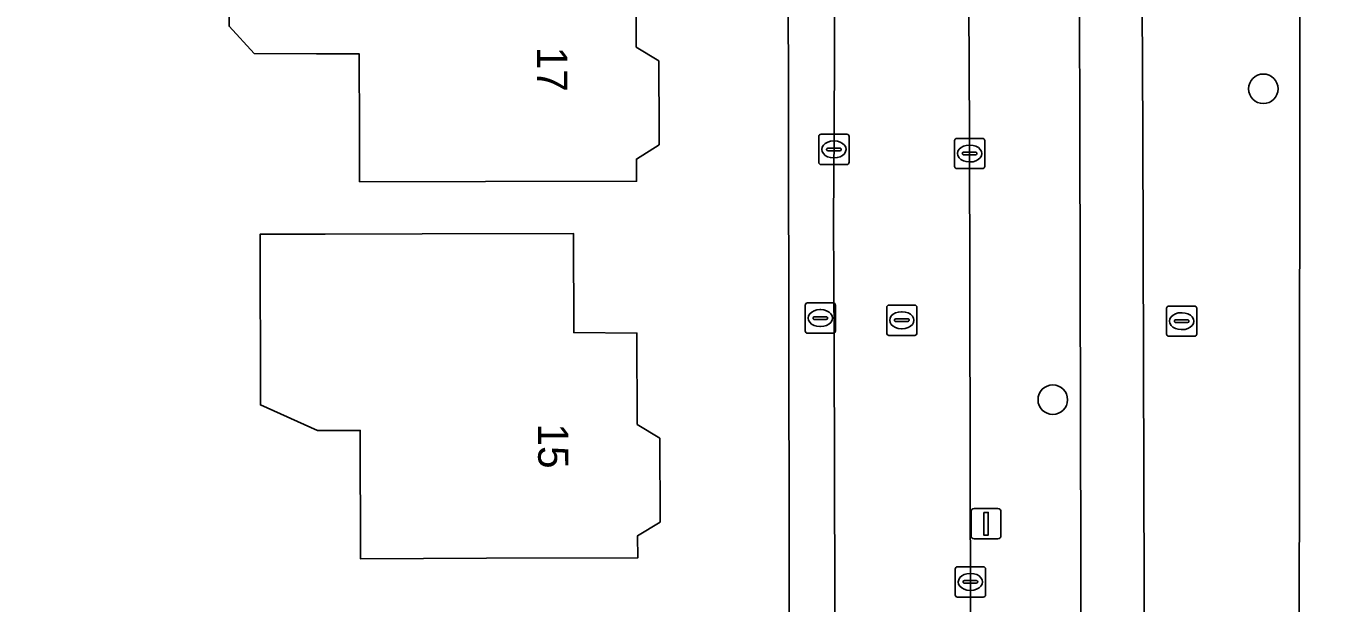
# Model space of a CAD drawing. Extents: x 160455 to 162082, y 388339 to 389736.
# Drawn here: x 160990.1 to 161032.93, y 388484.44 to 388503.52 of the extents above; entities that cross this region are included whole.
import ezdxf

# ---------------------------------------------------------------- set-up
doc = ezdxf.new("R2010")
doc.units = 0
for name, color, linetype in [('IMGEO_Berm_groen', 7, 'Continuous'), ('IMGEO_Boom', 7, 'Continuous'), ('IMGEO_Brandkraan', 7, 'Continuous'), ('IMGEO_Erf', 7, 'Continuous'), ('IMGEO_Fietspad_gesloten', 7, 'Continuous'), ('IMGEO_Kolk', 7, 'Continuous'), ('IMGEO_Lichtmast', 7, 'Continuous'), ('IMGEO_Pand', 7, 'Continuous'), ('IMGEO_Pand_nummerreeks', 7, 'Continuous'), ('IMGEO_Rijbaan_lokaal_gesloten', 7, 'Continuous'), ('IMGEO_Rijbaan_lokaal_open', 7, 'Continuous'), ('IMGEO_Rioolput', 7, 'Continuous'), ('IMGEO_Voetpad_open', 7, 'Continuous')]:
    doc.layers.add(name, color=color, linetype=linetype)

msp = doc.modelspace()

# ---------------------------------------------------------------- linework, layer by layer
at = {"layer": 'IMGEO_Berm_groen'}
msp.add_lwpolyline([(161032.227, 388500), (161032.231, 388503.917), (161032.193, 388520.283), (161029.121, 388520.276), (161029.136, 388504.228), (161027.02, 388504.221), (161027.033, 388500), (161027.148, 388462.179), (161031.576, 388462.237), (161031.753, 388467.74), (161032.004, 388475.58), (161032.208, 388481.936)], close=True, dxfattribs=at)
for points in [[(161024.953, 388500), (161024.943, 388504.232), (161021.289, 388504.243), (161021.304, 388500), (161021.377, 388467.669), (161021.401, 388466.075), (161021.412, 388465.493)], [(161022.511, 388462.16), (161025.043, 388462.172), (161024.953, 388500)]]:
    msp.add_lwpolyline(points, dxfattribs=at)
at = {"layer": 'IMGEO_Boom'}
for centre in [(161031.022, 388501.444), (161024.06, 388491.163)]:
    msp.add_circle(centre, 0.489, dxfattribs=at)
at = {"layer": 'IMGEO_Brandkraan'}
for p, q in [((161015.947, 388494.362), (161016.799, 388494.362)), ((161015.872, 388493.436), (161015.872, 388494.288)), ((161016.174, 388493.905), (161016.572, 388493.905)), ((161016.36, 388494.142), (161016.385, 388494.142)), ((161016.873, 388494.288), (161016.873, 388493.436)), ((161016.131, 388493.856), (161016.131, 388493.868)), ((161016.569, 388493.819), (161016.171, 388493.819)), ((161016.383, 388493.582), (161016.358, 388493.582)), ((161016.615, 388493.868), (161016.615, 388493.856)), ((161016.799, 388493.362), (161015.947, 388493.362))]:
    msp.add_line(p, q, dxfattribs=at)
for points in [[(161015.947, 388494.362), (161016.799, 388494.362)], [(161015.872, 388493.436), (161015.872, 388494.288)], [(161016.873, 388494.288), (161016.873, 388493.436)], [(161016.799, 388493.362), (161015.947, 388493.362)]]:
    msp.add_lwpolyline(points, dxfattribs=at)
for centre, radius, start, end in [((161015.949, 388494.286), 0.0765, 91.552, 178.448), ((161015.949, 388494.286), 0.0765, 91.552, 178.448), ((161016.797, 388494.286), 0.0765, 1.552, 88.448), ((161016.797, 388494.286), 0.0765, 1.552, 88.448), ((161016.171, 388493.865), 0.0403, 85.8775, 175.7526), ((161016.576, 388493.867), 0.0386, 1.7309, 96.639), ((161016.168, 388493.855), 0.0366, 178.938, 274.7102), ((161016.572, 388493.862), 0.043, 264.8664, 352.4533), ((161015.949, 388493.438), 0.0765, 181.552, 268.448), ((161015.949, 388493.438), 0.0765, 181.552, 268.448), ((161016.797, 388493.438), 0.0765, 271.552, 358.448), ((161016.797, 388493.438), 0.0765, 271.552, 358.448)]:
    msp.add_arc(centre, radius, start, end, dxfattribs=at)
for centre, major_axis, ratio, start_param, end_param in [((161016.359, 388493.862), (-0.387, 0.002), 0.722429, 4.712389, 7.853982), ((161016.384, 388493.862), (-0.39, 0.002), 0.717154, 1.570796, 4.712389)]:
    msp.add_ellipse(centre, major_axis=major_axis, ratio=ratio, start_param=start_param, end_param=end_param, dxfattribs=at)
at = {"layer": 'IMGEO_Erf'}
msp.add_lwpolyline([(161015.378, 388466.056), (161015.323, 388500), (161015.314, 388505.844), (161015.227, 388546.422)], dxfattribs=at)
for points in [[(161001.116, 388509.103), (161008.174, 388509.116), (161008.197, 388505.827), (161010.281, 388505.821), (161010.286, 388502.822), (161011.038, 388502.364), (161011.042, 388500), (161011.043, 388499.594), (161010.294, 388499.122), (161010.295, 388498.386), (161005.296, 388498.377), (161001.136, 388498.369), (161001.133, 388500), (161001.128, 388502.6), (160999.709, 388502.598), (160997.654, 388502.606), (160996.823, 388503.51), (160996.81, 388509.093), (160997.809, 388509.095)], [(161008.208, 388496.661), (161008.217, 388493.382), (161010.309, 388493.364), (161010.319, 388490.345), (161011.071, 388489.888), (161011.081, 388487.118), (161010.332, 388486.665), (161010.334, 388485.932), (161005.335, 388485.918), (161001.166, 388485.906), (161001.157, 388490.146), (161000, 388490.144), (160999.748, 388490.144), (160997.859, 388490.992), (160997.846, 388496.637), (161000, 388496.642), (161003.209, 388496.649)]]:
    msp.add_lwpolyline(points, close=True, dxfattribs=at)
at = {"layer": 'IMGEO_Fietspad_gesloten'}
for points in [[(161024.585, 388652.068), (161024.689, 388629.73), (161024.704, 388621.181), (161024.714, 388616.416), (161024.95, 388506.373), (161024.943, 388504.232), (161024.953, 388500), (161025.043, 388462.172), (161025.055, 388453.649), (161025.21, 388408.793)], [(161027.174, 388453.634), (161027.148, 388462.179), (161027.033, 388500), (161027.02, 388504.221), (161027, 388522.563), (161027, 388522.588), (161026.975, 388527.496), (161026.785, 388616.408), (161026.775, 388621.128), (161026.768, 388629.75), (161026.737, 388652.186)]]:
    msp.add_lwpolyline(points, dxfattribs=at)
at = {"layer": 'IMGEO_Kolk'}
for p, q in [((161016.397, 388499.94), (161017.249, 388499.94)), ((161016.322, 388499.014), (161016.322, 388499.866)), ((161016.624, 388499.483), (161017.022, 388499.483)), ((161016.81, 388499.72), (161016.835, 388499.72)), ((161017.323, 388499.866), (161017.323, 388499.014)), ((161020.81, 388498.878), (161020.81, 388499.73)), ((161020.885, 388499.804), (161021.737, 388499.804)), ((161021.298, 388499.584), (161021.323, 388499.584)), ((161021.811, 388499.73), (161021.811, 388498.878)), ((161016.581, 388499.434), (161016.581, 388499.446)), ((161017.019, 388499.397), (161016.621, 388499.397)), ((161016.833, 388499.16), (161016.808, 388499.16)), ((161017.065, 388499.446), (161017.065, 388499.434)), ((161021.069, 388499.298), (161021.069, 388499.31)), ((161021.507, 388499.261), (161021.109, 388499.261)), ((161021.112, 388499.347), (161021.51, 388499.347)), ((161021.553, 388499.31), (161021.553, 388499.298)), ((161017.249, 388498.94), (161016.397, 388498.94)), ((161021.737, 388498.804), (161020.885, 388498.804)), ((161021.321, 388499.024), (161021.296, 388499.024)), ((161020.835, 388484.711), (161020.835, 388485.563)), ((161020.91, 388485.637), (161021.762, 388485.637)), ((161021.323, 388485.417), (161021.348, 388485.417)), ((161021.836, 388485.563), (161021.836, 388484.711)), ((161021.094, 388485.131), (161021.094, 388485.143)), ((161021.532, 388485.094), (161021.134, 388485.094)), ((161021.137, 388485.18), (161021.535, 388485.18)), ((161021.578, 388485.143), (161021.578, 388485.131)), ((161021.762, 388484.637), (161020.91, 388484.637)), ((161021.346, 388484.857), (161021.321, 388484.857))]:
    msp.add_line(p, q, dxfattribs=at)
for points in [[(161016.397, 388499.94), (161017.249, 388499.94)], [(161016.322, 388499.014), (161016.322, 388499.866)], [(161017.323, 388499.866), (161017.323, 388499.014)], [(161020.81, 388498.878), (161020.81, 388499.73)], [(161020.885, 388499.804), (161021.737, 388499.804)], [(161021.811, 388499.73), (161021.811, 388498.878)], [(161017.249, 388498.94), (161016.397, 388498.94)], [(161021.737, 388498.804), (161020.885, 388498.804)], [(161020.835, 388484.711), (161020.835, 388485.563)], [(161020.91, 388485.637), (161021.762, 388485.637)], [(161021.836, 388485.563), (161021.836, 388484.711)], [(161021.762, 388484.637), (161020.91, 388484.637)]]:
    msp.add_lwpolyline(points, dxfattribs=at)
for centre, radius, start, end in [((161016.399, 388499.864), 0.0765, 91.552, 178.448), ((161016.399, 388499.864), 0.0765, 91.552, 178.448), ((161017.247, 388499.864), 0.0765, 1.552, 88.448), ((161017.247, 388499.864), 0.0765, 1.552, 88.448), ((161016.621, 388499.443), 0.0403, 85.8775, 175.7526), ((161017.026, 388499.445), 0.0386, 1.7309, 96.639), ((161020.887, 388499.728), 0.0765, 91.552, 178.448), ((161020.887, 388499.728), 0.0765, 91.552, 178.448), ((161021.735, 388499.728), 0.0765, 1.552, 88.448), ((161021.735, 388499.728), 0.0765, 1.552, 88.448), ((161016.618, 388499.433), 0.0366, 178.938, 274.7102), ((161017.022, 388499.44), 0.043, 264.8664, 352.4533), ((161021.109, 388499.307), 0.0403, 85.8775, 175.7526), ((161021.106, 388499.297), 0.0366, 178.938, 274.7102), ((161021.51, 388499.304), 0.043, 264.8664, 352.4533), ((161021.514, 388499.309), 0.0386, 1.7309, 96.639), ((161016.399, 388499.016), 0.0765, 181.552, 268.448), ((161016.399, 388499.016), 0.0765, 181.552, 268.448), ((161017.247, 388499.016), 0.0765, 271.552, 358.448), ((161017.247, 388499.016), 0.0765, 271.552, 358.448), ((161020.887, 388498.88), 0.0765, 181.552, 268.448), ((161020.887, 388498.88), 0.0765, 181.552, 268.448), ((161021.735, 388498.88), 0.0765, 271.552, 358.448), ((161021.735, 388498.88), 0.0765, 271.552, 358.448), ((161020.912, 388485.561), 0.0765, 91.552, 178.448), ((161020.912, 388485.561), 0.0765, 91.552, 178.448), ((161021.76, 388485.561), 0.0765, 1.552, 88.448), ((161021.76, 388485.561), 0.0765, 1.552, 88.448), ((161021.134, 388485.14), 0.0403, 85.8775, 175.7526), ((161021.131, 388485.13), 0.0366, 178.938, 274.7102), ((161021.535, 388485.137), 0.043, 264.8664, 352.4533), ((161021.539, 388485.142), 0.0386, 1.7309, 96.639), ((161020.912, 388484.713), 0.0765, 181.552, 268.448), ((161020.912, 388484.713), 0.0765, 181.552, 268.448), ((161021.76, 388484.713), 0.0765, 271.552, 358.448), ((161021.76, 388484.713), 0.0765, 271.552, 358.448)]:
    msp.add_arc(centre, radius, start, end, dxfattribs=at)
for centre, major_axis, ratio, start_param, end_param in [((161016.809, 388499.44), (-0.387, 0.002), 0.722429, 4.712389, 7.853982), ((161016.834, 388499.44), (-0.39, 0.002), 0.717154, 1.570796, 4.712389), ((161021.297, 388499.304), (-0.387, 0.002), 0.722429, 4.712389, 7.853982), ((161021.322, 388499.304), (-0.39, 0.002), 0.717154, 1.570796, 4.712389), ((161021.322, 388485.137), (-0.387, 0.002), 0.722429, 4.712389, 7.853982), ((161021.347, 388485.137), (-0.39, 0.002), 0.717154, 1.570796, 4.712389)]:
    msp.add_ellipse(centre, major_axis=major_axis, ratio=ratio, start_param=start_param, end_param=end_param, dxfattribs=at)
at = {"layer": 'IMGEO_Lichtmast'}
for p, q in [((161021.457, 388487.561), (161022.247, 388487.561)), ((161022.247, 388487.561), (161021.457, 388487.561)), ((161021.357, 388486.661), (161021.357, 388487.461)), ((161021.357, 388487.461), (161021.357, 388486.661)), ((161022.347, 388487.461), (161022.347, 388486.661)), ((161022.347, 388486.661), (161022.347, 388487.461)), ((161022.247, 388486.561), (161021.457, 388486.561)), ((161021.457, 388486.561), (161022.247, 388486.561))]:
    msp.add_line(p, q, dxfattribs=at)
msp.add_lwpolyline([(161021.777, 388487.436), (161021.927, 388487.436), (161021.927, 388486.686), (161021.777, 388486.686), (161021.777, 388487.436)], dxfattribs=at)
for centre, start, end in [((161021.457, 388487.461), 90, 180), ((161021.457, 388487.461), 90, 180), ((161022.247, 388487.461), 0, 90), ((161022.247, 388487.461), 360, 90), ((161021.457, 388486.661), 180, 270), ((161021.457, 388486.661), 180, 270), ((161022.247, 388486.661), 270, 0), ((161022.247, 388486.661), 270, 0)]:
    msp.add_arc(centre, 0.1, start, end, dxfattribs=at)
at = {"layer": 'IMGEO_Pand'}
for points in [[(161005.296, 388498.377), (161010.295, 388498.386), (161010.294, 388499.122), (161011.043, 388499.594), (161011.042, 388500), (161011.038, 388502.364), (161010.286, 388502.822), (161010.281, 388505.821), (161008.197, 388505.827), (161008.174, 388509.116), (161001.116, 388509.103), (160997.809, 388509.095), (160996.81, 388509.093), (160996.823, 388503.51), (160997.654, 388502.606), (160999.709, 388502.598), (161001.128, 388502.6), (161001.133, 388500), (161001.136, 388498.369)], [(161003.209, 388496.649), (161000, 388496.642), (160997.846, 388496.637), (160997.859, 388490.992), (160999.748, 388490.144), (161000, 388490.144), (161001.157, 388490.146), (161001.166, 388485.906), (161005.335, 388485.918), (161010.334, 388485.932), (161010.332, 388486.665), (161011.081, 388487.118), (161011.071, 388489.888), (161010.319, 388490.345), (161010.309, 388493.364), (161008.217, 388493.382), (161008.208, 388496.661)]]:
    msp.add_lwpolyline(points, close=True, dxfattribs=at)
at = {"layer": 'IMGEO_Rijbaan_lokaal_gesloten'}
msp.add_lwpolyline([(161038.306, 388674.146), (161031.808, 388674.113), (161031.909, 388629.816), (161031.939, 388621.107), (161032.194, 388527.118), (161032.214, 388522.986), (161032.211, 388522.593), (161032.193, 388520.283), (161032.231, 388503.917), (161032.227, 388500), (161032.208, 388481.936), (161032.004, 388475.58), (161038.842, 388475.598)], dxfattribs=at)
at = {"layer": 'IMGEO_Rijbaan_lokaal_open'}
msp.add_lwpolyline([(161016.867, 388480.625), (161016.875, 388465.995), (161021.401, 388466.075), (161021.377, 388467.669), (161021.304, 388500), (161021.289, 388504.243), (161021.281, 388506.384), (161021.281, 388506.524), (161021.221, 388540.482), (161021.2, 388548.919), (161016.702, 388548.912), (161016.705, 388546.804), (161016.718, 388542.707), (161016.738, 388534.213), (161016.723, 388530.311), (161016.749, 388522.452), (161016.777, 388518.23), (161016.782, 388509.772), (161016.857, 388505.543), (161016.827, 388500), (161016.812, 388497.114), (161016.826, 388493.013), (161016.848, 388484.613)], close=True, dxfattribs=at)
at = {"layer": 'IMGEO_Rioolput'}
for p, q in [((161018.567, 388493.365), (161018.567, 388494.217)), ((161018.642, 388494.291), (161019.494, 388494.291)), ((161019.055, 388494.071), (161019.08, 388494.071)), ((161019.568, 388494.217), (161019.568, 388493.365)), ((161027.821, 388493.334), (161027.821, 388494.186)), ((161027.896, 388494.26), (161028.748, 388494.26)), ((161028.309, 388494.04), (161028.334, 388494.04)), ((161028.822, 388494.186), (161028.822, 388493.334)), ((161018.826, 388493.785), (161018.826, 388493.797)), ((161019.264, 388493.748), (161018.866, 388493.748)), ((161018.869, 388493.834), (161019.267, 388493.834)), ((161019.078, 388493.511), (161019.053, 388493.511)), ((161019.31, 388493.797), (161019.31, 388493.785)), ((161028.08, 388493.754), (161028.08, 388493.766)), ((161028.518, 388493.717), (161028.12, 388493.717)), ((161028.123, 388493.803), (161028.521, 388493.803)), ((161028.332, 388493.48), (161028.307, 388493.48)), ((161028.564, 388493.766), (161028.564, 388493.754)), ((161019.494, 388493.291), (161018.642, 388493.291)), ((161028.748, 388493.26), (161027.896, 388493.26))]:
    msp.add_line(p, q, dxfattribs=at)
for points in [[(161018.567, 388493.365), (161018.567, 388494.217)], [(161018.642, 388494.291), (161019.494, 388494.291)], [(161019.568, 388494.217), (161019.568, 388493.365)], [(161027.821, 388493.334), (161027.821, 388494.186)], [(161027.896, 388494.26), (161028.748, 388494.26)], [(161028.822, 388494.186), (161028.822, 388493.334)], [(161019.494, 388493.291), (161018.642, 388493.291)], [(161028.748, 388493.26), (161027.896, 388493.26)]]:
    msp.add_lwpolyline(points, dxfattribs=at)
for centre, radius, start, end in [((161018.644, 388494.215), 0.0765, 91.552, 178.448), ((161018.644, 388494.215), 0.0765, 91.552, 178.448), ((161019.492, 388494.215), 0.0765, 1.552, 88.448), ((161019.492, 388494.215), 0.0765, 1.552, 88.448), ((161027.898, 388494.184), 0.0765, 91.552, 178.448), ((161027.898, 388494.184), 0.0765, 91.552, 178.448), ((161028.746, 388494.184), 0.0765, 1.552, 88.448), ((161028.746, 388494.184), 0.0765, 1.552, 88.448), ((161018.866, 388493.794), 0.0403, 85.8775, 175.7526), ((161018.863, 388493.784), 0.0366, 178.938, 274.7102), ((161019.267, 388493.791), 0.043, 264.8664, 352.4533), ((161019.271, 388493.796), 0.0386, 1.7309, 96.639), ((161028.12, 388493.763), 0.0403, 85.8775, 175.7526), ((161028.117, 388493.753), 0.0366, 178.938, 274.7102), ((161028.521, 388493.76), 0.043, 264.8664, 352.4533), ((161028.525, 388493.765), 0.0386, 1.7309, 96.639), ((161018.644, 388493.367), 0.0765, 181.552, 268.448), ((161018.644, 388493.367), 0.0765, 181.552, 268.448), ((161019.492, 388493.367), 0.0765, 271.552, 358.448), ((161019.492, 388493.367), 0.0765, 271.552, 358.448), ((161027.898, 388493.336), 0.0765, 181.552, 268.448), ((161027.898, 388493.336), 0.0765, 181.552, 268.448), ((161028.746, 388493.336), 0.0765, 271.552, 358.448), ((161028.746, 388493.336), 0.0765, 271.552, 358.448)]:
    msp.add_arc(centre, radius, start, end, dxfattribs=at)
for centre, major_axis, ratio, start_param, end_param in [((161019.054, 388493.791), (-0.387, 0.002), 0.722429, 4.712389, 7.853982), ((161019.079, 388493.791), (-0.39, 0.002), 0.717154, 1.570796, 4.712389), ((161028.308, 388493.76), (-0.387, 0.002), 0.722429, 4.712389, 7.853982), ((161028.333, 388493.76), (-0.39, 0.002), 0.717154, 1.570796, 4.712389)]:
    msp.add_ellipse(centre, major_axis=major_axis, ratio=ratio, start_param=start_param, end_param=end_param, dxfattribs=at)
at = {"layer": 'IMGEO_Voetpad_open'}
for points in [[(161015.058, 388617.261), (161015.222, 388548.437), (161001.342, 388548.405), (160985.162, 388548.37), (160985.172, 388546.374), (160990.022, 388546.381), (160997.719, 388546.392), (161000, 388546.397), (161008.109, 388546.416), (161015.227, 388546.422), (161015.314, 388505.844), (161015.323, 388500), (161015.378, 388466.056)], [(161016.875, 388465.499), (161016.875, 388465.995), (161016.867, 388480.625), (161016.848, 388484.613), (161016.826, 388493.013), (161016.812, 388497.114), (161016.827, 388500), (161016.857, 388505.543), (161016.782, 388509.772), (161016.777, 388518.23), (161016.749, 388522.452), (161016.723, 388530.311), (161016.738, 388534.213), (161016.718, 388542.707), (161016.705, 388546.804)]]:
    msp.add_lwpolyline(points, dxfattribs=at)

# ---------------------------------------------------------------- texts
at = {"layer": 'IMGEO_Pand_nummerreeks'}
for s, rotation, p in [('17', 270.1079, (161007.006, 388502.832)), ('15', 270.1927, (161007.04, 388490.372))]:
    msp.add_text(s, height=1, rotation=rotation, dxfattribs=at).set_placement(p)

doc.saveas('drawing.dxf')
